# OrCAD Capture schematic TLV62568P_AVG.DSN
size D; title: TLV62568P 1-A High Efficiency Synchronous Buck Converter; rev: 1.0; note: Datasheet: SLVSD89B                EVM: SLVUB20A; note: Synchronous Step Down Converter; note: in SOT Package
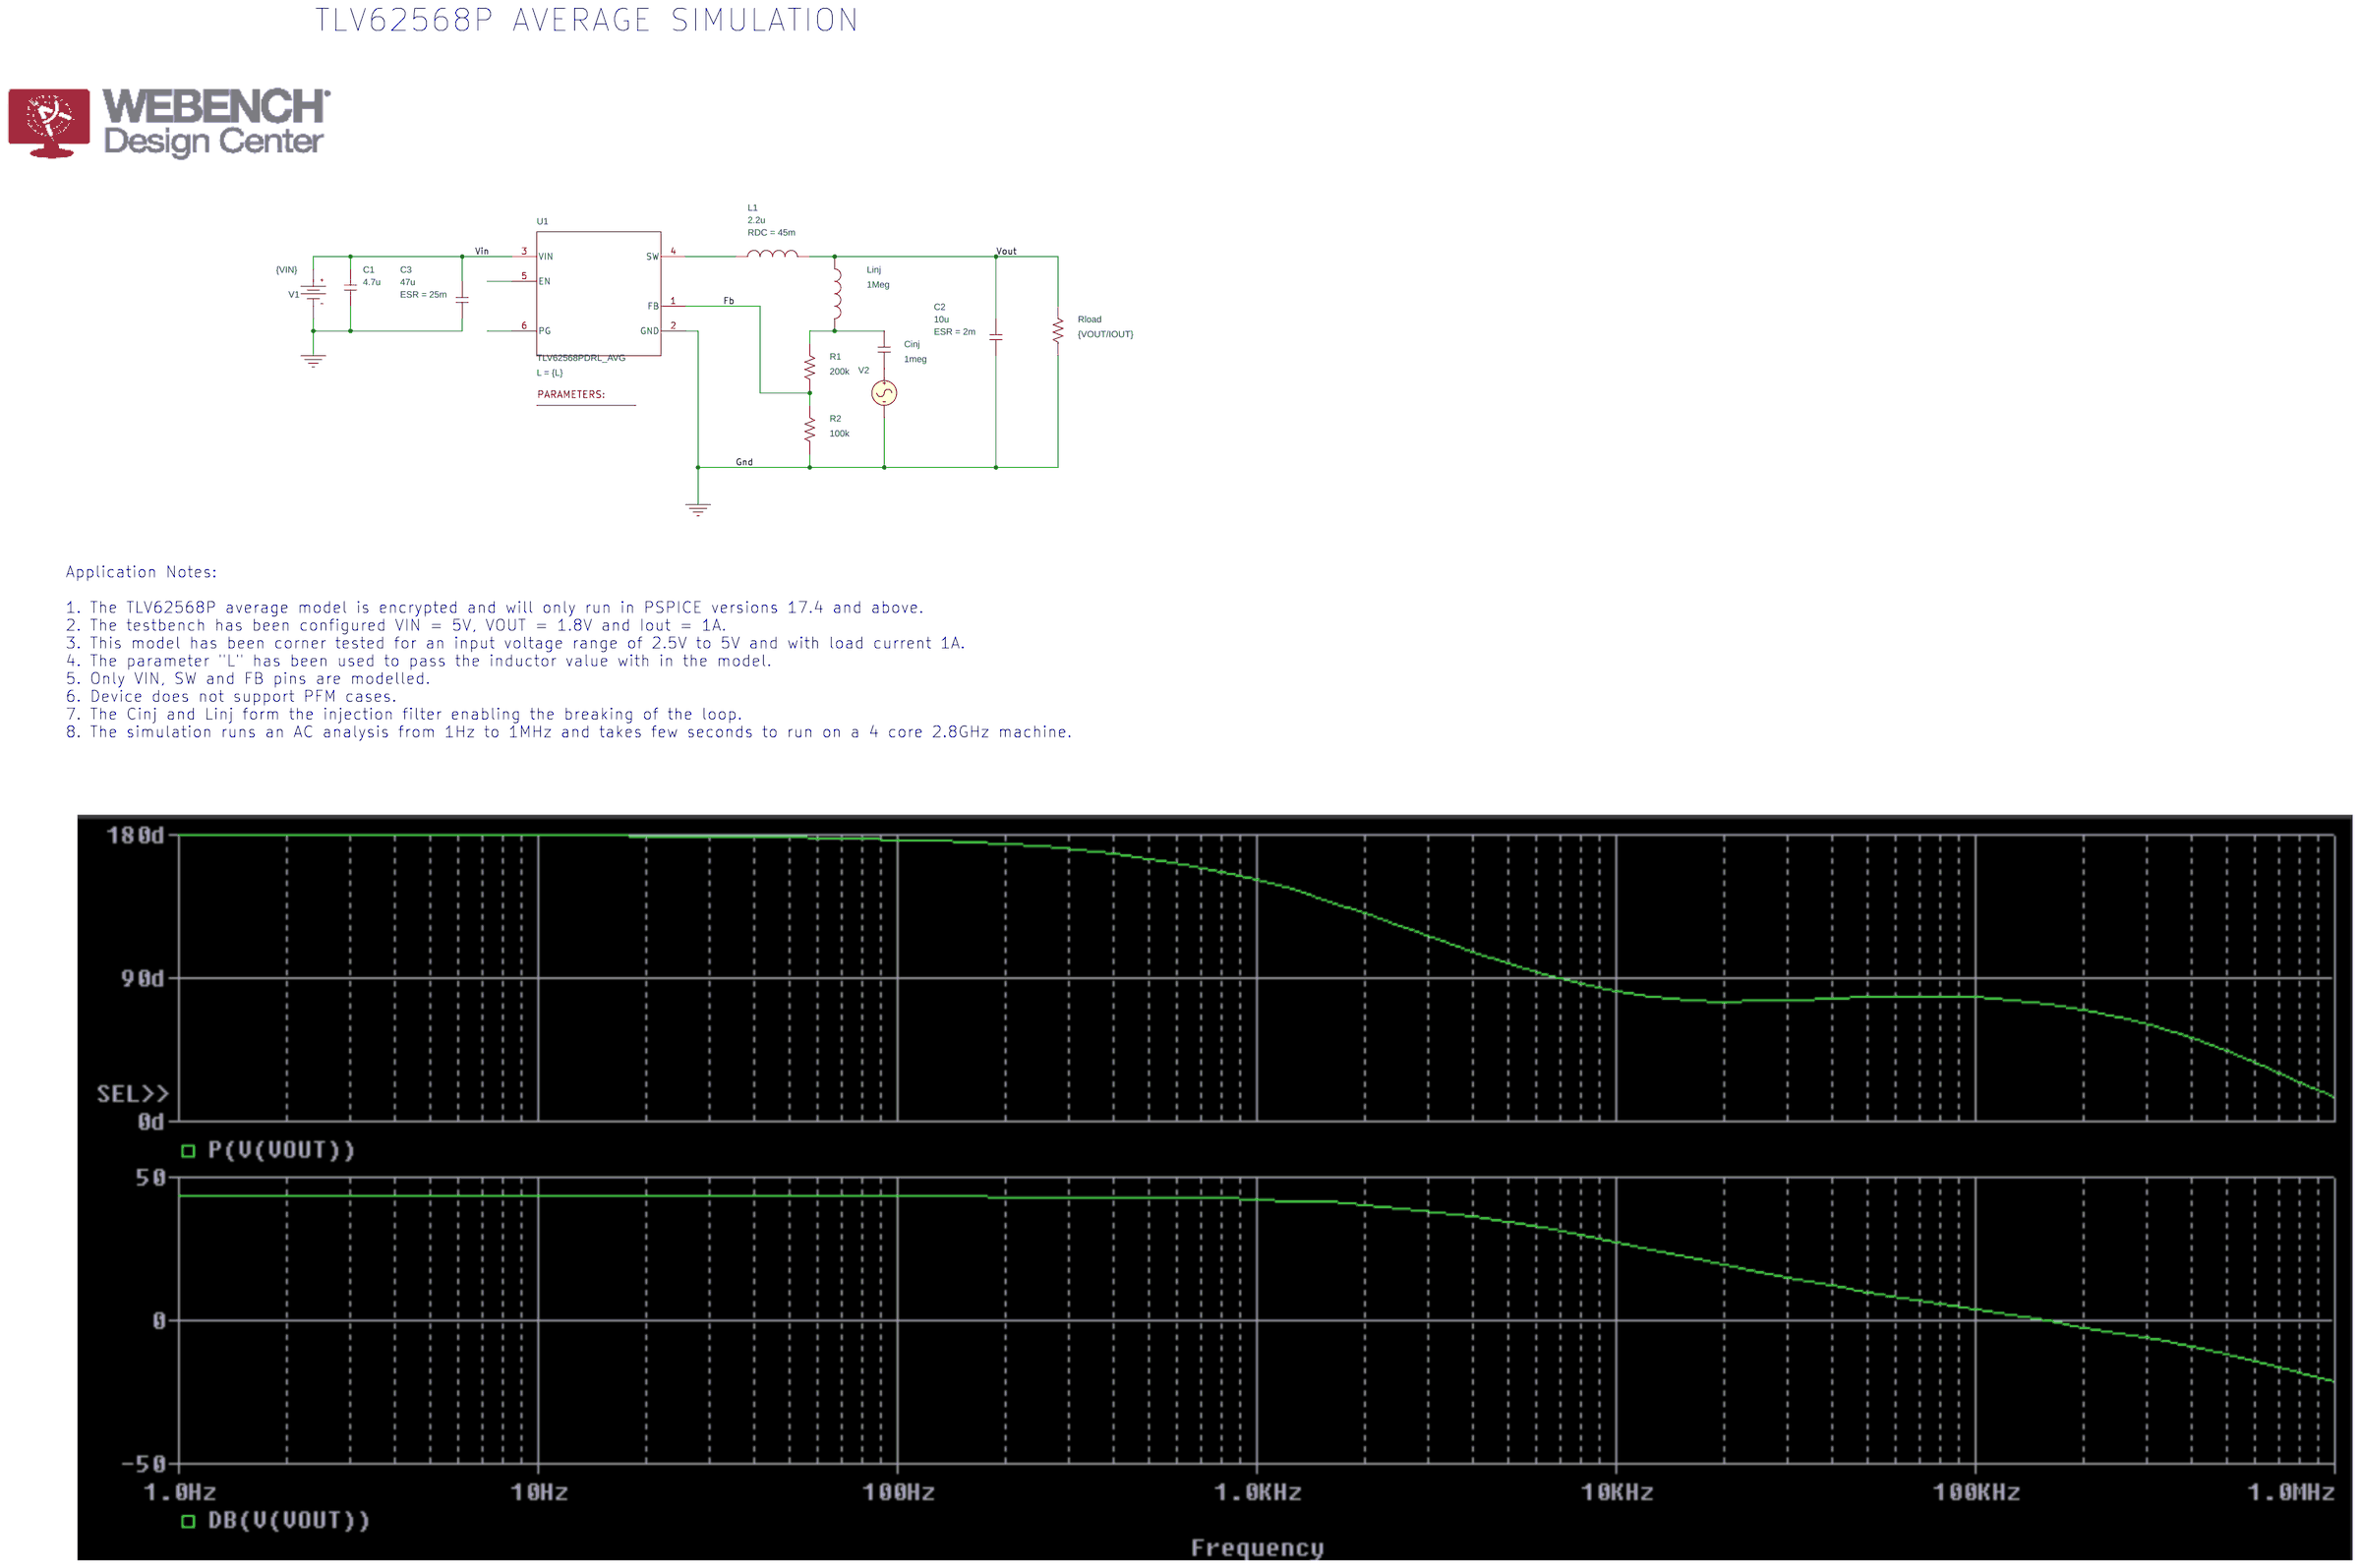
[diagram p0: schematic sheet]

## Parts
1  PARAM
C1  4.7u  [cap196]
C2  10u  [RAD/CK05]
C3  47u  [RAD/CK05]
Cinj  1meg  [RAD/CK05]
L1  2.2u  [DISC/.350x.175/LS.200x.100/.034]
Linj  1Meg  [DISC/.350x.175/LS.200x.100/.034]
R1  200k  [AXRC05]
R2  100k  [AXRC05]
Rload  {VOUT/IOUT}  [AXRC05]
U1  TLV62568PDRL_AVG  [DRL0006A]
V1  VDC
V2  VAC

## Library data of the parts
1 = PARAM: L: 2.2u; VIN: 5; VOUT: 1.8
C1 Cinj = C
C2 = C: AppProp: InductiveSlave:;SRF:;PrevCap:10u;PrevESL:; ESR: 2m
C3 = C: AppProp: InductiveSlave:;SRF:;PrevCap:10u;PrevESL:; ESR: 25m
L1 = L: AppProp: SRF:; RDC: 45m
Linj = L
R1 R2 Rload = R
U1 = TLV62568PDRL_AVG: L: {L}
V1 = VDC: DC: {VIN}
V2 = VAC

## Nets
Vin: C1.2 C3.1 U1.3(VIN) V1.0(+)
0: C1.1 C2.2 C3.2 R2.1 Rload.1 U1.2(GND) V1.1(-) V2.2(-)
Fb: R1.1 R2.2 U1.1(FB)
Vout: C2.1 L1.2 Linj.1 Rload.2
N16769956: L1.1 U1.4(SW)
N16787246: Cinj.1 Linj.2 R1.2
N16788397: Cinj.2 V2.1(+)

Not connected (* = marked no-connect by the designer): U1 5(EN) 6(PG)

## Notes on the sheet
- TLV62568P AVERAGE SIMULATION
- Application Notes:
  1. The TLV62568P average model is encrypted and will only run in PSPICE versions 17.4 and above.
  2. The testbench has been configured VIN = 5V, VOUT = 1.8V and Iout = 1A.
  3. This model has been corner tested for an input voltage range of 2.5V to 5V and with load current 1A.
  4. The parameter "L" has been used to pass the inductor value with in the model.
  5. Only VIN, SW and FB pins are modelled.
  6. Device does not support PFM cases.
  7. The Cinj and Linj form the injection filter enabling the breaking of the loop.
  8. The simulation runs an AC analysis from 1Hz to 1MHz and takes few seconds to run on a 4 core 2.8GHz machine.
